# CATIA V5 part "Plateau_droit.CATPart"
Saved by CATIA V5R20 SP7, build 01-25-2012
Part number: Plateau_droit
Bounding box of the stored display mesh (mm): x 90 to 210, y -4.99 to 60, z -62.49 to 57.49
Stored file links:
  D:\IFMA\COURS\2A\projet balance IAO\catia\Plateau_droit.CATPart
  D:\IFMA\COURS\2A\projet balance IAO\catia\Ass_projet_balance.CATProduct
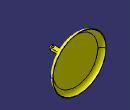
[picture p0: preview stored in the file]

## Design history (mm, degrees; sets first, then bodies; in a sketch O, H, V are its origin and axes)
Set1
  Plane1 "Plan_plateau_droit": linked copy from another document
  Point1 "Point.G": linked copy from another document
  Point2 "Point.F": linked copy from another document
Body1 (main body)
  Point3 "Point.G": stored without definition
  Sketch1 on Plane1, origin (0, 0, 0), H (1, 0, 0), V (0, 1, 0)
    arc A1 centre (150, 0) radius 5 from (145, 0) to (155, 0) ccw
    point P1 (150, 0)
    line L1 (155, 0) -> (155, 50)
    line L2 (155, 50) -> (145, 50)
    line L3 (145, 50) -> (145, 0)
    reference projected point E1 (150, 0) from Point1
    reference projected point E2 (150, 30) from Point2
    distance L1 L3 = 10
    distance L2 E2 = 20
    tangency: L1 A1, L3 A1
    horizontal: L2 H
    vertical: L3 V
    coincidence: P1 E1
  Pad1: profile Sketch1, direction (0, 0, -1), length 5
  Sketch2 on start face of Pad1, origin (0, 0, 0), H (1, 0, 0), V (0, 1, 0)
    circle A1 centre (150, 30) radius 2.5
    point P1 (150, 30)
    circle A2 centre (150, 0) radius 2.5
    point P2 (150, 0)
    reference projected point E1 (150, 30) from Point2
    reference projected point E2 (150, 0) from Point1
    radius A2 = 2.5
    radius A1 = 2.5
    coincidence: P1 E1, P2 E2
  Pocket1: profile Sketch2, direction (0, 0, -1), through (limit type 6)
  Sketch3 on face of Pad1 from Sketch1.L2, origin (0, 50, 0), H (-1, 0, 0), V (0, 0, 1)
    circle A1 centre (-150, -2.5) radius 60
    point P1 (-150, -2.5)
    reference projected point E1 (-150, 0) from Point2
    reference projected point E2 (-150, 0) from Point2
    radius A1 = 60
    distance P1 E1 H = 0
    distance P1 E2 V = 2.5
  Pad2: profile Sketch3, direction (0, 1, 0), length 10
  Sketch4 on end face of Pad2, origin (0, 60, 0), H (-1, 0, 0), V (0, 0, 1)
    circle A1 centre (-150, -2.5) radius 59
    point P1 (-150, -2.5)
    reference projected point E1 (-150, 0) from Point2
    reference projected point E2 (-150, 0) from Point2
    reference projected circle E3 centre (-150, -2.5) radius 60 from edge [face of Pad2 from Sketch3.A1 | end face of Pad2]
    distance P1 E1 H = 0
    distance P1 E2 V = 2.5
    distance A1 E3 = 1
  Pocket2: profile Sketch4, direction (0, -1, 0), length 9
  Fillet1: radius 9, on edge [face of Pocket2 from Sketch4.A1 | end face of Pocket2]
  Fillet2: radius 10, on edge [start face of Pad2 | face of Pad2 from Sketch3.A1]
